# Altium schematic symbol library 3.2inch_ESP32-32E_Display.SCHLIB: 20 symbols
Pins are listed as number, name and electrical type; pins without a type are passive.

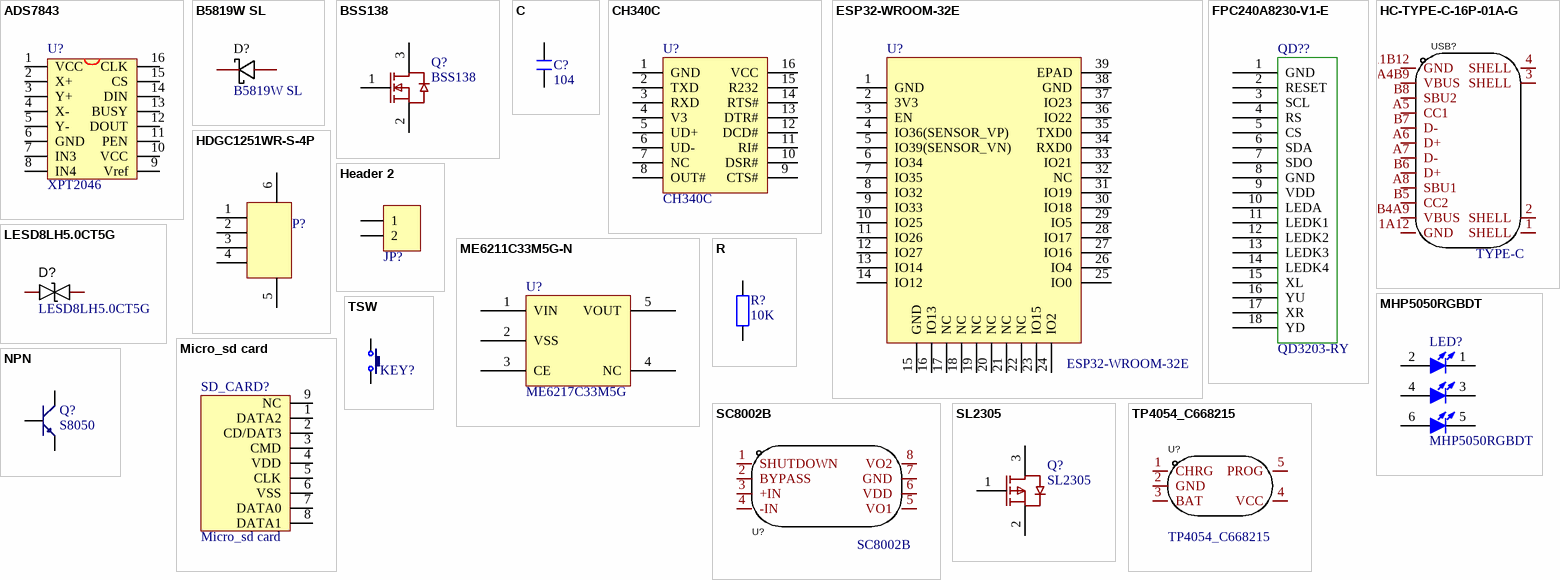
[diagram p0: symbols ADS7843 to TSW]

## ADS7843
designator U?, comment XPT2046
footprint SSOP16
pins: 1 VCC, 2 X+, 3 Y+, 4 X-, 5 Y-, 6 GND, 7 IN3, 8 IN4, 9 Vref, 10 VCC, 11 PEN, 12 DOUT, 13 BUSY, 14 DIN, 15 CS, 16 CLK

## B5819W SL
designator D?
Manufacturer: CJ(江苏长电/长晶); Symbol: B5819W_C8598; Add into BOM: yes; Forward Voltage (Vf@If): 600mV@1A; Reverse Voltage (Vr): 40V; Average Rectified Current (Io): 1A
footprint SOD-123_L2.7-W1.6-LS3.7-RD-1
pins: 1 -, 2 +

## BSS138
designator Q?
footprint SOT-23-3_L2.9-W1.3-P1.90-LS2.4-BR
pins: 1 G, 2 S, 3 D

## C
designator C?, comment 104
无极性贴片电容; 版权归属: 源创客; 材质: X7R
footprint C 0603 (无极性贴片电容)
pins: 1, 2

## CH340C
designator U?
USB转串口IC
footprint SOP-16_L10.0-W3.9-P1.27-LS6.0-BL
pins: 1 GND, 2 TXD, 3 RXD, 4 V3, 5 UD+, 6 UD-, 7 NC, 8 OUT#, 9 CTS#, 10 DSR#, 11 RI#, 12 DCD#, 13 DTR#, 14 RTS#, 15 R232, 16 VCC

## ESP32-WROOM-32E
designator U?
ESP32-WROOM-32E module
footprint ESP32-WROOM-32E
pins: 1 GND, 2 3V3, 3 EN, 4 IO36(SENSOR_VP), 5 IO39(SENSOR_VN), 6 IO34, 7 IO35, 8 IO32, 9 IO33, 10 IO25, 11 IO26, 12 IO27, 13 IO14, 14 IO12, 15 GND, 16 IO13, 17 NC, 18 NC, 19 NC, 20 NC, 21 NC, 22 NC, 23 IO15, 24 IO2, 25 IO0, 26 IO4, 27 IO16, 28 IO17, 29 IO5, 30 IO18, 31 IO19, 32 NC, 33 IO21, 34 RXD0, 35 TXD0, 36 IO22, 37 IO23, 38 GND, 39 EPAD

## FPC240A8230-V1-E
designator QD??, comment QD3203-RY
footprint QD-TFT3222_18P_0.8mm (3.2inch TFT IPS)
pins: 1 GND, 2 RESET, 3 SCL, 4 RS, 5 CS, 6 SDA, 7 SDO, 8 GND, 9 VDD, 10 LEDA, 11 LEDK1, 12 LEDK2, 13 LEDK3, 14 LEDK4, 15 XL, 16 YU, 17 XR, 18 YD

## HC-TYPE-C-16P-01A-G
designator USB?, comment TYPE-C
Manufacturer: HCTL(华灿天禄); Name: HC-TYPE-C-16P-01A-G; Add into BOM: yes; Gender: 母座; Number of Contacts: 16; Number of Ports: 1
3D model USB-C-SMD_G-SWITCH_GT-USB-7010EN
footprint USB-C-SMD_G-SWITCH_GT-USB-7010EN
footprint USB-C-SMD_G-SWITCH_GT-USB-7010EN
pins: 1 SHELL, 2 SHELL, 3 SHELL, 4 SHELL, A1B12 GND, A4B9 VBUS, A5 CC1, A6 D+, A7 D-, A8 SBU1, B1A12 GND, B4A9 VBUS, B5 CC2, B6 D+, B7 D-, B8 SBU2

## HDGC1251WR-S-4P
designator P?  (value not drawn)
footprint CONN-SMD_4P-P1.25_HDGC-HDGC1251WR-S-4P
pins: 1, 2, 3, 4, 5, 6

## Header 2
designator JP?  (value not drawn)
2P接插件; BOM名称: 20*2P接插件; 版权归属: 源创客
footprint CONN-SMD_HC-1.25-2PLT
pins: 1, 2

## LESD8LH5.0CT5G
designator D?
Manufacturer: LRC(乐山无线电); Add into BOM: yes; Reverse Stand-Off Voltage (Vrwm): 5V; Maximum Clamping Voltage: 11.5V; Peak Pulse Current (Ipp)@10/1000us: 3.5A@8/20us; Breakdown Voltage: 5.5V; Type: TVS
footprint SOD-882_L1.0-W0.6-BI
pins: 1, 2

## ME6211C33M5G-N
designator U?, comment ME6217C33M5G
稳压芯片
footprint SOT-23-5_L3.0-W1.7-P0.95-LS2.8-BL
pins: 1 VIN, 2 VSS, 3 CE, 4 NC, 5 VOUT

## MHP5050RGBDT
designator LED?
RGB LED
footprint LED-ARRAY-SMD_6P-L5.0-W5.0-TR-RD
pins: 1 K, 2 A, 3 K, 4 A, 5 K, 6 A

## Micro_sd card
designator SD_CARD?
miniSD卡卡槽
footprint MicroTF
pins: 1 DATA2, 2 CD/DAT3, 3 CMD, 4 VDD, 5 CLK, 6 VSS, 7 DATA0, 8 DATA1, 9 NC

## NPN
designator Q?, comment S8050
8050/BCW846/BCW847
footprint SOT-23R
footprint NPN
pins: 1 E, 2 B, 3 C

## R
designator R?, comment 10K
贴片电阻; 版权归属: 源创客
footprint R0603
pins: 1, 2

## SC8002B
designator U?
Manufacturer: FM(富满); Add into BOM: yes; Speaker Channels: 单声道; Output Power: 2.5Wx1@4Ω; Supply Voltage: 2V~5V
footprint SOP-8_L4.9-W3.9-P1.27-LS6.0-BL
pins: 1 SHUTDOWN, 2 BYPASS, 3 +IN, 4 -IN, 5 VO1, 6 VDD, 7 GND, 8 VO2

## SL2305
designator Q?
P-mos
footprint SOT-23
pins: 1 G, 2 S, 3 D

## TP4054_C668215
designator U?
Manufacturer: UMW(友台半导体); Manufacturer Part: TP4054; Add into BOM: yes; Supply Voltage: 6.5V; Maximum Charge Current: 500mA; Type of Battery: 锂离子/聚合物; Number of Cells: 1
footprint TSOT-23-5_L2.9-W1.6-P0.95-LS2.8-BR
pins: 1 CHRG, 2 GND, 3 BAT, 4 VCC, 5 PROG

## TSW
designator KEY?, comment 3x6x5  (value not drawn)
轻触开关; BOM名称: 3x6轻触开关; 版权归属: 源创客
footprint TSW SMD-3*4*2.5 (3*4*2.5mm)
pins: 1, 2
